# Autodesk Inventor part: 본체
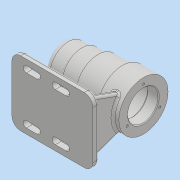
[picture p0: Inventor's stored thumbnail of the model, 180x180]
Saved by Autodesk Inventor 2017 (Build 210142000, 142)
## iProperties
Part Number: 본체
Material: 일반
Document SubType Name: Modeling
Designer: MRC
Density: 1 g/cm^3
Appearance: 기본값
Author: MRC
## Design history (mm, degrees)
sketch "스케치1"
  geometry: L1 (-56, 0)-(56, 0); L2 (-56, 0)-(-56, 25); L3 (-56, 25)-(-32, 25); L4 (-32, 25)-(-32, 27); L5 (-32, 27)-(-10, 27); L6 (-10, 27)-(-10, 30); L7 (-10, 30)-(24, 30); L8 (24, 30)-(24, 34); L9 (24, 34)-(56, 34); L10 (56, 34)-(56, 0); L11 (56, 21)-(41, 21); L12 (41, 21)-(41, 24); L13 (41, 24)-(-13, 24); L14 (-13, 24)-(-13, 21); L15 (-13, 21)-(-25, 21); L16 (-25, 21)-(-25, 17.5); L17 (-25, 17.5)-(-43, 17.5); L18 (-43, 17.5)-(-43, 16); L19 (-43, 16)-(-47, 16); L20 (-47, 16)-(-47, 10.5); L21 (-47, 10.5)-(-50, 10.5); L22 (-50, 10.5)-(-50, 0); 2 further points
  constraints: 44 end point, 20 perpendicular, 2 point on line, 1 coincident, 1 horizontal, 1 midpoint, 1 vertical
  dimensions: "d0" = 112 distance of L1.start L1.end; "d1" = 50 diameter of L3 L1; "d2" = 54 diameter of L5 L1; "d3" = 60 diameter of L7 L1; "d4" = 68 diameter of L9 L1; "d5" = 24 distance of L2.end L3.end; "d6" = 46 distance between parallel lines of L6 L2; "d7" = 80 distance between parallel lines of L8 L2; "d8" = 42 diameter of L11 L1; "d9" = 48 diameter of L13 L1; "d10" = 42 diameter of L15 L1; "d11" = 21 diameter of L21 L1; "d12" = 32 diameter of L19 L1; "d13" = 35 diameter of L17 L1; "d14" = 15 distance of L11.start L11.end; "d15" = 54 distance of L12.end L13.end; "d16" = 12 distance of L14.end L15.end; "d17" = 18 distance of L16.end L17.end; "d18" = 4 distance of L18.end L19.end; "d19" = 3 distance of L20.end L21.end
revolve "회전1" sketch "스케치1" stored, may be unused: angle "d20" = 90 deg
fillet "모깎기1" dims "d21" = 0.3
fillet "모깎기2" dims "d22" = 3
chamfer "모따기1" distance "d23" = 1; stored, may be unused: second distance "d24" = 2, angle "d25" = 45 deg
fillet "모깎기3" dims "d26" = 8
fillet "모깎기4" dims "d27" = 3
sketch "스케치2"
  geometry: C1 r 34 at (0, 0) reference; 1 further point
  constraints: 1 horizontal alignment
  dimensions: "d28" = 26 distance of point (-26, 0) C1.centre
hole "구멍1" sketch "스케치2" at (-26, 0) diameter "d29" = 3.242; stored, may be unused: countersink angle "d33" = 90 deg, drill point angle "d35" = 118 deg; dims "d30" = 8, "d31" = 4, "d32" = 2, "d34" = 11
sketch "스케치3"
  geometry: L1 (-56, -62)-(56, -62); L2 (56, -62)-(56, -70); L3 (56, -70)-(-56, -70); L4 (-56, -70)-(-56, -62); 2 further points
  constraints: 8 end point, 2 parallel, 1 horizontal, 1 midpoint, 1 perpendicular, 1 vertical alignment
  dimensions: "d39" = 112 distance of L2.end L3.end; "d40" = 8 distance of L1.end L2.end; "d41" = 70 distance from line of point (0, 0) L3
extrude "돌출1" join sketch "스케치3" stored distance "d42" = 90; taper "d43" = 0 deg
node "작업 평면1"
sketch "스케치4"
  geometry: L1 (21.591, 45.342)-(8, 8); L2 (0, 8)-(0, 0) reference; L3 (90, 8)-(0, 8) reference; L4 (68.409, 45.342)-(82, 8); L5 (90, 0)-(90, 8) reference; A1 r 34 centre (45, 70) between (68.409, 45.342) and (21.591, 45.342) reference; 1 further point
  constraints: 4 end point, 2 point on circle, 2 point on line
  dimensions: "d45" = 8 distance from line of L1.end L2; "d46" = 110 deg angle of L1 L3; "d47" = 8 distance from line of L4.end L5; "d48" = 110 deg angle of L4 L3
extrude "돌출2" join sketch "스케치4" distance "d49" = 8; taper "d50" = 0 deg
sketch "스케치5"
  geometry: L1 (-29, -62)-(-24.783, -46.262); L2 (56, -62)-(-56, -62) reference; L3 (48, -24.658)-(48, -62) reference; 1 further point
  constraints: 2 end point, 1 point on line
  dimensions: "d51" = 105 deg angle of L1 L2; "d53" = 77 distance from line of L3 L1.start
feature "리브1" sketch "스케치5" dims "d54" = 1, "d55" = 8, "d56" = 0, "d57" = 0, "d58" = 1, "d59" = 1
sketch "스케치6"
  geometry: L1 (0, 0)-(0, -90) reference; L2 (20, -78)-(35, -78); L3 (20, -82.5)-(35, -82.5); L4 (35, -73.5)-(20, -73.5); L5 (60, -78)-(75, -78); L6 (60, -82.5)-(75, -82.5); L7 (75, -73.5)-(60, -73.5); A1 r 4.5 centre (20, -78) between (20, -73.5) and (20, -82.5); A2 r 4.5 centre (35, -78) between (35, -82.5) and (35, -73.5); A3 r 4.5 centre (60, -78) between (60, -73.5) and (60, -82.5); A4 r 4.5 centre (75, -78) between (75, -82.5) and (75, -73.5); 3 further points
  constraints: 16 end point, 8 point on circle, 8 tangent, 4 centre point, 2 midpoint, 2 parallel, 2 point on line, 1 horizontal
  dimensions: "d60" = 20 distance from line of L2.start L1; "d61" = 15 distance of L2.start L2.end; "d62" = 25 distance of L5.start L2.end; "d63" = 15 distance of L5.start L5.end; "d64" = 9 distance between parallel lines of L4 L3; "d65" = 33 distance from line of L2 point (56, -45); "d66" = 9 distance between parallel lines of L6 L7
extrude "돌출3" cut sketch "스케치6" stored distance "d67" = 8; taper "d68" = 0 deg
sketch "스케치7"
  geometry: L1 (0, 0)-(0, -90) reference; 2 further points
  constraints: 1 horizontal alignment, 1 other
  dimensions: "d69" = 12 distance from line of point (12, -45) L1
feature "엠보싱1" sketch "스케치7" dims "d0" = 112, "d1" = 50, "d2" = 54, "d3" = 60, "d4" = 68, "d5" = 24, "d6" = 46, "d7" = 80, "d8" = 42, "d9" = 48, "d10" = 42, "d11" = 21, "d12" = 32, "d13" = 35, "d14" = 15, "d15" = 54, "d16" = 12, "d17" = 18, "d18" = 4, "d19" = 3, "d70" = 0.5, "d71" = 0
fillet "모깎기5" dims "d72" = 12
fillet "모깎기6" dims "d73" = 3
fillet "모깎기7" dims "d74" = 3
fillet "모깎기8" dims "d75" = 3
node "솔리드1"
pattern_circular "원형 패턴1" dims angle "d37" = 360 deg
mirror "미러1"
other parameters: "d44" = -8
